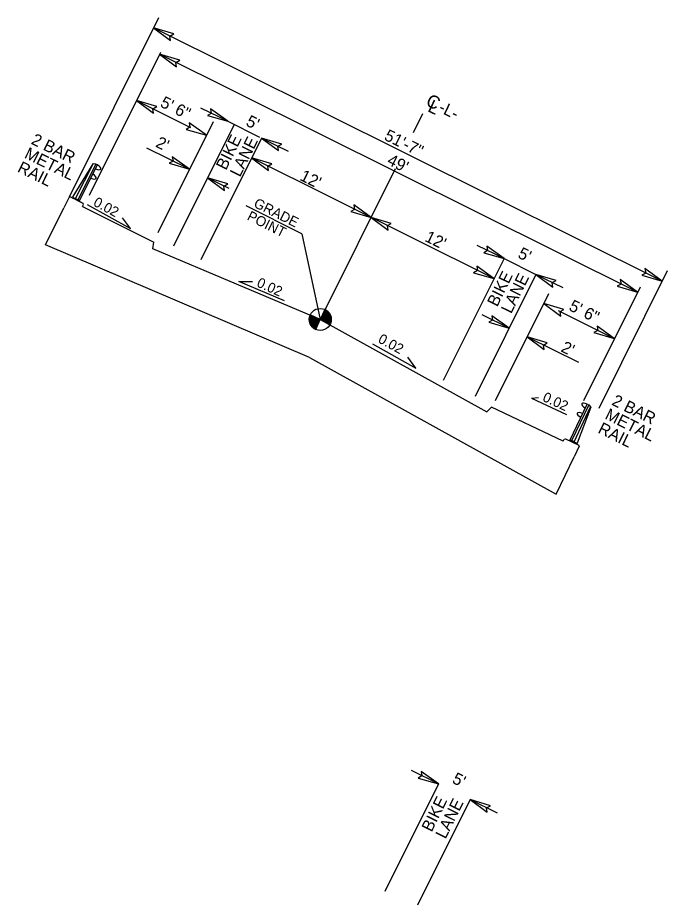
# Model space of a CAD drawing. Extents: x 1518247 to 1523638, y 635234 to 639927.
# Drawn here: x 1519564 to 1520214, y 638461 to 639349 of the extents above; entities that cross this region are included whole.
import ezdxf

# ---------------------------------------------------------------- set-up
doc = ezdxf.new("R2010")
doc.units = 0
for name, color, linetype in [('Old_Level_1', 7, 'Continuous'), ('Prop Dimension', 7, 'Continuous'), ('Prop Dimension Text', 7, 'Continuous'), ('Typical Arrow Superelevation CELL', 7, 'Continuous'), ('Typical Berm Information CELL', 7, 'Continuous'), ('Typical Sidewalk and Rail CELL', 7, 'Continuous'), ('Typical Text Centerline CELL', 7, 'Continuous')]:
    doc.layers.add(name, color=color, linetype=linetype)

msp = doc.modelspace()

# ---------------------------------------------------------------- linework, layer by layer
at = {"layer": 'Old_Level_1'}
for p, q in [((1519969.26, 639253.41), (1519959.79, 639234.38)), ((1519941.93, 639198.12), (1519866.99, 639047.58)), ((1519592.03, 639122.34), (1519610.48, 639159.39)), ((1519633.99, 639162.6), (1519677.35, 639138.41)), ((1519848.63, 639133.21), (1519792.95, 639161.3)), ((1519677.35, 639138.41), (1519669.09, 639149.31)), ((1519848.63, 639133.21), (1519866.99, 639047.58)), ((1519856.16, 639009.41), (1519592.03, 639122.34)), ((1519866.99, 639047.6), (1519699.45, 639118.29)), ((1519785.53, 639085.51), (1519799.2, 639085.68)), ((1519831.24, 639066.13), (1519785.53, 639085.51)), ((1519856.94, 639052.05), (1519866.99, 639047.58)), ((1519866.99, 639047.58), (1519856.94, 639052.05)), ((1519871.47, 639057.62), (1519866.99, 639047.58)), ((1519862.5, 639037.55), (1519866.99, 639047.58)), ((1519866.99, 639047.58), (1519877.02, 639043.1)), ((1519867, 639047.6), (1520033.75, 638955.08)), ((1519919.35, 639023.03), (1519962.71, 638998.85)), ((1519856.16, 639009.41), (1520102.9, 638872.78)), ((1519962.71, 638998.85), (1519954.45, 639009.74)), ((1520102.9, 638872.78), (1520120.82, 638910.09))]:
    msp.add_line(p, q, dxfattribs=at)
for points in [[(1519720.37, 639333.23), (1519700.11, 639339.31), (1519717.22, 639326.65), (1519716.48, 639331.15)], [(1519726.51, 639306.91), (1519706.25, 639312.98), (1519723.36, 639300.33), (1519722.63, 639304.83)], [(1519703.41, 639260.51), (1519683.15, 639266.59), (1519700.27, 639253.93), (1519699.53, 639258.44)], [(1519754.1, 639251.67), (1519774.44, 639245.86), (1519757.16, 639258.29), (1519757.95, 639253.8)], [(1519732.78, 639237.67), (1519753.12, 639231.87), (1519735.83, 639244.3), (1519736.63, 639239.8)], [(1519828.4, 639223.03), (1519808.14, 639229.1), (1519825.25, 639216.45), (1519824.52, 639220.95)], [(1519715.91, 639203.79), (1519736.24, 639197.98), (1519718.96, 639210.41), (1519719.76, 639205.92)], [(1519818.51, 639203.16), (1519798.25, 639209.23), (1519815.36, 639196.57), (1519814.63, 639201.08)], [(1519774.47, 639183.12), (1519754.21, 639189.2), (1519771.32, 639176.54), (1519770.59, 639181.04)], [(1519897.49, 639155.5), (1519917.82, 639149.7), (1519900.54, 639162.13), (1519901.34, 639157.63)], [(1519938.08, 639143.62), (1519917.82, 639149.7), (1519934.94, 639137.04), (1519934.2, 639141.55)], [(1520030.53, 639114.29), (1520050.87, 639108.48), (1520033.59, 639120.91), (1520034.38, 639116.42)], [(1520020.44, 639094.29), (1520040.78, 639088.49), (1520023.5, 639100.92), (1520024.3, 639096.42)], [(1520188.68, 639091.75), (1520209.02, 639085.95), (1520191.74, 639098.38), (1520192.53, 639093.88)], [(1520102.9, 639086.59), (1520082.64, 639092.67), (1520099.75, 639080.01), (1520099.02, 639084.51)], [(1520164.05, 639080.75), (1520184.39, 639074.95), (1520167.11, 639087.38), (1520167.9, 639082.88)], [(1520110.76, 639057.5), (1520090.5, 639063.58), (1520107.61, 639050.92), (1520106.88, 639055.42)], [(1520035.52, 639044.67), (1520055.86, 639038.87), (1520038.58, 639051.3), (1520039.37, 639046.8)], [(1520140.76, 639034.33), (1520161.1, 639028.52), (1520143.82, 639040.95), (1520144.61, 639036.46)], [(1520094.08, 639024), (1520073.82, 639030.08), (1520090.94, 639017.42), (1520090.2, 639021.93)], [(1519964.89, 638588.7), (1519985.23, 638582.9), (1519967.95, 638595.33), (1519968.74, 638590.83)], [(1520037.26, 638561.01), (1520017, 638567.08), (1520034.11, 638554.42), (1520033.38, 638558.93)]]:
    msp.add_lwpolyline(points, close=True, dxfattribs=at)
for points in [[(1519866.29, 639046.02), (1519856.39, 639050.45)], [(1519866.38, 639046.22), (1519856.43, 639050.67)], [(1519866.47, 639046.42), (1519856.5, 639050.88)], [(1519866.56, 639046.63), (1519856.57, 639051.09)], [(1519866.65, 639046.83), (1519856.64, 639051.3)], [(1519866.74, 639047.03), (1519856.72, 639051.5)], [(1519866.83, 639047.23), (1519856.79, 639051.71)], [(1519866.92, 639047.43), (1519856.88, 639051.91), (1519856.88, 639051.91)], [(1519877.85, 639045.97), (1519868.19, 639050.28)], [(1519877.9, 639046.19), (1519868.28, 639050.48)], [(1519877.92, 639046.42), (1519868.37, 639050.68)], [(1519877.94, 639046.65), (1519868.46, 639050.88)], [(1519877.96, 639046.88), (1519868.55, 639051.09)], [(1519877.96, 639047.12), (1519868.64, 639051.29)], [(1519877.96, 639047.36), (1519868.73, 639051.49)], [(1519877.97, 639047.6), (1519868.82, 639051.69)], [(1519877.97, 639047.84), (1519868.91, 639051.89)], [(1519877.97, 639048.08), (1519869, 639052.09)], [(1519877.94, 639048.33), (1519869.09, 639052.29)], [(1519877.92, 639048.58), (1519869.18, 639052.49)], [(1519877.9, 639048.83), (1519869.27, 639052.69)], [(1519877.88, 639049.08), (1519869.36, 639052.89)], [(1519877.83, 639049.35), (1519869.45, 639053.09)], [(1519877.79, 639049.61), (1519869.54, 639053.29)], [(1519877.72, 639049.88), (1519869.63, 639053.49)], [(1519877.68, 639050.14), (1519869.72, 639053.69)], [(1519877.61, 639050.41), (1519869.81, 639053.9)], [(1519877.52, 639050.69), (1519869.9, 639054.1)], [(1519877.44, 639050.97), (1519869.99, 639054.3)], [(1519877.35, 639051.25), (1519870.08, 639054.5)], [(1519877.24, 639051.54), (1519870.17, 639054.7)], [(1519877.13, 639051.83), (1519870.26, 639054.9)], [(1519876.99, 639052.13), (1519870.35, 639055.1)], [(1519876.84, 639052.44), (1519870.44, 639055.3)], [(1519876.68, 639052.75), (1519870.53, 639055.5)], [(1519876.5, 639053.07), (1519870.61, 639055.7)], [(1519876.3, 639053.4), (1519870.7, 639055.9)], [(1519876.08, 639053.74), (1519870.79, 639056.1)], [(1519875.84, 639054.09), (1519870.88, 639056.3)], [(1519875.57, 639054.45), (1519870.97, 639056.5)], [(1519875.23, 639054.84), (1519871.06, 639056.71)], [(1519874.85, 639055.25), (1519871.15, 639056.91)], [(1519874.39, 639055.7), (1519871.24, 639057.11)], [(1519873.79, 639056.21), (1519871.33, 639057.31)], [(1519872.85, 639056.87), (1519871.42, 639057.51)], [(1519865.39, 639044.02), (1519856, 639048.21)], [(1519865.3, 639043.82), (1519856, 639047.97)], [(1519865.21, 639043.61), (1519856, 639047.73)], [(1519865.12, 639043.41), (1519856, 639047.49)], [(1519865.03, 639043.21), (1519856, 639047.25)], [(1519864.94, 639043.01), (1519856, 639047.01)], [(1519864.85, 639042.81), (1519856.02, 639046.76)], [(1519865.48, 639044.22), (1519856.03, 639048.44)], [(1519865.57, 639044.42), (1519856.05, 639048.67)], [(1519864.76, 639042.61), (1519856.05, 639046.51)], [(1519865.66, 639044.62), (1519856.07, 639048.9)], [(1519864.68, 639042.41), (1519856.07, 639046.26)], [(1519864.59, 639042.21), (1519856.11, 639046)], [(1519865.75, 639044.82), (1519856.12, 639049.12)], [(1519865.84, 639045.02), (1519856.14, 639049.35)], [(1519864.5, 639042.01), (1519856.15, 639045.74)], [(1519865.93, 639045.22), (1519856.19, 639049.57)], [(1519864.41, 639041.81), (1519856.2, 639045.48)], [(1519866.02, 639045.42), (1519856.23, 639049.8)], [(1519864.32, 639041.61), (1519856.24, 639045.22)], [(1519866.11, 639045.62), (1519856.28, 639050.02)], [(1519864.23, 639041.41), (1519856.31, 639044.94)], [(1519866.2, 639045.82), (1519856.32, 639050.24)], [(1519864.14, 639041.21), (1519856.38, 639044.67)], [(1519864.05, 639041), (1519856.46, 639044.39)], [(1519863.96, 639040.8), (1519856.55, 639044.11)], [(1519863.87, 639040.6), (1519856.64, 639043.83)], [(1519863.78, 639040.4), (1519856.75, 639043.54)], [(1519863.69, 639040.2), (1519856.89, 639043.24)], [(1519863.6, 639040), (1519857.02, 639042.94)], [(1519863.51, 639039.8), (1519857.18, 639042.63)], [(1519863.42, 639039.6), (1519857.33, 639042.32)], [(1519863.33, 639039.4), (1519857.51, 639042)], [(1519863.24, 639039.2), (1519857.71, 639041.67)], [(1519877.06, 639043.19), (1519877.06, 639043.19), (1519867.03, 639047.67)], [(1519877.15, 639043.39), (1519867.12, 639047.87)], [(1519877.22, 639043.6), (1519867.21, 639048.07)], [(1519877.31, 639043.8), (1519867.3, 639048.27)], [(1519877.38, 639044.01), (1519867.39, 639048.48)], [(1519877.44, 639044.22), (1519867.48, 639048.68)], [(1519877.51, 639044.43), (1519867.57, 639048.88)], [(1519877.58, 639044.64), (1519867.66, 639049.08)], [(1519877.65, 639044.85), (1519867.74, 639049.28)], [(1519877.69, 639045.07), (1519867.83, 639049.48)], [(1519877.74, 639045.3), (1519867.92, 639049.68)], [(1519877.78, 639045.52), (1519868.01, 639049.88)], [(1519877.83, 639045.74), (1519868.1, 639050.08)], [(1519863.15, 639039), (1519857.93, 639041.33)], [(1519863.06, 639038.8), (1519858.2, 639040.97)], [(1519862.97, 639038.6), (1519858.49, 639040.6)], [(1519862.88, 639038.4), (1519858.82, 639040.21)], [(1519862.79, 639038.19), (1519859.2, 639039.8)], [(1519862.7, 639037.99), (1519859.71, 639039.33)], [(1519862.61, 639037.79), (1519860.34, 639038.81)], [(1519862.52, 639037.59), (1519861.43, 639038.08)]]:
    msp.add_lwpolyline(points, dxfattribs=at)
msp.add_circle((1519866.98, 639047.57), 10.99, dxfattribs=at)
for start, end in [(155.93113, 245.93113), (335.93113, 65.93113)]:
    msp.add_arc((1519866.98, 639047.57), 10.99, start, end, dxfattribs=at)
at = {"layer": 'Prop Dimension'}
for p, q in [((1519705.15, 639349.44), (1519615.77, 639169.89)), ((1520209.02, 639085.95), (1519700.11, 639339.31)), ((1519707.03, 639314.56), (1519635.79, 639171.46)), ((1520184.39, 639074.95), (1519706.25, 639312.98)), ((1519683.15, 639266.59), (1519737.15, 639239.68)), ((1519774.44, 639245.86), (1519747.53, 639259.02)), ((1519774.44, 639245.86), (1519806.21, 639230.05)), ((1519759.74, 639245.18), (1519704.45, 639134.13)), ((1519780.84, 639242.68), (1519720.14, 639120.76)), ((1519808.14, 639229.1), (1519747.44, 639107.17)), ((1519808.14, 639229.1), (1519835.05, 639215.94)), ((1519736.24, 639197.98), (1519693.62, 639218.83)), ((1520040.78, 639088.49), (1519798.25, 639209.23)), ((1519754.21, 639189.2), (1519775.49, 639178.79)), ((1520050.87, 639108.48), (1520023.96, 639121.64)), ((1520050.87, 639108.48), (1519990.08, 638986.37)), ((1520050.87, 639108.48), (1520082.64, 639092.67)), ((1520214.07, 639096.09), (1520145.6, 638958.55)), ((1520082.64, 639092.67), (1520021.85, 638970.56)), ((1520082.64, 639092.67), (1520109.55, 639079.51)), ((1520186.85, 639079.89), (1520130.25, 638966.19)), ((1520095.24, 639073.09), (1520041.97, 638966.1)), ((1520055.86, 639038.87), (1520028.95, 639052.03)), ((1520105.12, 639056.42), (1520161.1, 639028.52)), ((1520073.82, 639030.08), (1520125.43, 639004.84)), ((1519985.23, 638582.9), (1519958.32, 638596.06)), ((1519985.23, 638582.9), (1519931.63, 638475.23)), ((1520017, 638567.08), (1519964.38, 638461.38)), ((1520017, 638567.08), (1520043.91, 638553.92))]:
    msp.add_line(p, q, dxfattribs=at)
at = {"layer": 'Typical Arrow Superelevation CELL'}
msp.add_line((1520078.18, 638968.81), (1520085.45, 638969.45), dxfattribs=at)
at = {"layer": 'Typical Berm Information CELL'}
msp.add_line((1520078.18, 638968.81), (1520113.41, 638952.45), dxfattribs=at)
at = {"layer": 'Typical Sidewalk and Rail CELL'}
for p, q in [((1519615.77, 639169.89), (1519610.48, 639159.39)), ((1519615.77, 639169.89), (1519616.86, 639170.26)), ((1519629.91, 639163.69), (1519616.86, 639170.26)), ((1519619.96, 639168.59), (1519619.26, 639168.94)), ((1519627.77, 639164.66), (1519626.83, 639165.13)), ((1519629.31, 639160.45), (1519630.32, 639162.45)), ((1519629.31, 639160.45), (1519700.41, 639124.89)), ((1519630.32, 639162.45), (1519629.91, 639163.69)), ((1519699.45, 639118.29), (1519700.41, 639124.89)), ((1520033.75, 638955.08), (1520038.37, 638959.89)), ((1520110.09, 638925.6), (1520038.37, 638959.89)), ((1520110.09, 638925.6), (1520111.05, 638927.62)), ((1520111.05, 638927.62), (1520112.28, 638928.06)), ((1520112.28, 638928.06), (1520125.48, 638921.8)), ((1520125.86, 638920.71), (1520120.82, 638910.09)), ((1520125.86, 638920.71), (1520125.48, 638921.8))]:
    msp.add_line(p, q, dxfattribs=at)
for points in [[(1519644.14, 639202.11), (1519642.5, 639202.93), (1519639.69, 639203.17), (1519639.47, 639203.29), (1519619.42, 639170.43), (1519619.24, 639170.08), (1519626.24, 639166.56), (1519644.14, 639202.11), (1519642.5, 639202.93), (1519624.61, 639167.38), (1519622.26, 639168.56), (1519639.69, 639203.17)], [(1520133.87, 638962.88), (1520135.52, 638962.1), (1520137.44, 638960.03), (1520137.67, 638959.92), (1520124.04, 638923.92), (1520123.87, 638923.57), (1520116.8, 638926.93), (1520133.87, 638962.88), (1520135.52, 638962.1), (1520118.45, 638926.14), (1520120.82, 638925.02), (1520137.44, 638960.03)]]:
    msp.add_lwpolyline(points, dxfattribs=at)
for centre, major_axis, start_param, end_param in [((1519643.2, 639200.24), (4.43, -2.23), 0, 1.570796), ((1519638.5, 639190.92), (4.43, -2.23), 0, 1.570796), ((1519643.2, 639200.24), (4.43, -2.23), 4.712389, 6.283185), ((1519638.5, 639190.92), (4.43, -2.23), 4.712389, 6.283185), ((1520132.98, 638960.99), (-4.48, 2.13), 0, 1.570796), ((1520132.98, 638960.99), (-4.48, 2.13), 4.712389, 6.283185), ((1520128.5, 638951.57), (-4.48, 2.13), 0, 1.570796), ((1520128.5, 638951.57), (-4.48, 2.13), 4.712389, 6.283185)]:
    msp.add_ellipse(centre, major_axis=major_axis, ratio=0.42124, start_param=start_param, end_param=end_param, dxfattribs=at)

# ---------------------------------------------------------------- texts
at = {"layer": 'Old_Level_1'}
for s, height, rotation, p in [('0.02', 9.969, 331.95384, (1519639.22, 639161.83)), ('GRADE', 10.005, 333.53399, (1519799.57, 639160.55)), ('POINT', 10.005, 333.53399, (1519792.92, 639147.72)), ('0.02', 9.969, 335.9216, (1519802.68, 639080.84)), ('0.02', 9.969, 331.32219, (1519924.04, 639025.06))]:
    msp.add_text(s, height=height, rotation=rotation, dxfattribs=at).set_placement(p)
at = {"layer": 'Prop Dimension'}
for s, rotation, p in [('5\' 6"', 333.74084, (1519706, 639260.89)), ("5'", 333.74084, (1519791.76, 639241.98)), ('51\'-7"', 333.74084, (1519930.07, 639227.75)), ('2 BAR', 333.74084, (1519577.01, 639223.63)), ("2'", 333.74084, (1519701.44, 639220.68)), ('BIKE', 63.74084, (1519772.71, 639196.22)), ('LANE', 63.74084, (1519786.65, 639189.34)), ('METAL', 333.74084, (1519570.13, 639209.69)), ("49'", 333.74084, (1519932.96, 639203.15)), ('RAIL', 333.74084, (1519563.25, 639195.74)), ("12'", 333.74084, (1519845.67, 639187.43)), ("12'", 333.74084, (1519970.67, 639126.36)), ("5'", 333.74084, (1520063.73, 639109.81)), ('BIKE', 63.74084, (1520043.97, 639059.51)), ('LANE', 63.74084, (1520057.92, 639052.63)), ('5\' 6"', 333.74084, (1520114.8, 639057.25)), ("2'", 333.74084, (1520106.9, 639015.87)), ('2 BAR', 333.74084, (1520157.67, 638962.48)), ('METAL', 333.74084, (1520150.79, 638948.53)), ('RAIL', 333.74084, (1520143.91, 638934.59)), ("5'", 333.74084, (1519998.09, 638584.23)), ('BIKE', 63.74084, (1519978.33, 638533.93)), ('LANE', 63.74084, (1519992.28, 638527.05))]:
    msp.add_text(s, height=11.865, rotation=rotation, dxfattribs=at).set_placement(p)
at = {"layer": 'Prop Dimension Text'}
msp.add_text('-L-', height=11.962, rotation=333.89618, dxfattribs=at).set_placement((1519984.37, 639255.87))
at = {"layer": 'Typical Berm Information CELL'}
msp.add_text('0.02', height=9.969, rotation=335.7046, dxfattribs=at).set_placement((1520088.59, 638966.3))
at = {"layer": 'Typical Text Centerline CELL'}
for s, height, rotation, p in [('C', 13.08, 333.89618, (1519971.61, 639262.19)), ('L', 13.09, 333.84308, (1519973.55, 639256.27))]:
    msp.add_text(s, height=height, rotation=rotation, dxfattribs=at).set_placement(p)

doc.saveas('drawing.dxf')
